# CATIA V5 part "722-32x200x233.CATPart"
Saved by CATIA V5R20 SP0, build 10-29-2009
Part number: 722-32x200x233
Definition: NONE
Nomenclature: 722-32x200x233
Source: Unknown
Description: 722-32x200x233
Bounding box of the stored display mesh (mm): x -16 to 16, y -16 to 16, z -185 to 48
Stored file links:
  C:\Users\Utente\Desktop\IO LAVORO\3D X SITO CF\X SITO\722\722-32x200x233.CATPart
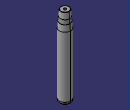
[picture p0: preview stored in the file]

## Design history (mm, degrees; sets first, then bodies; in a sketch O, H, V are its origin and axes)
Body1 "722-32x200x233" (main body)
  Solid1: solid without history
